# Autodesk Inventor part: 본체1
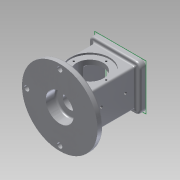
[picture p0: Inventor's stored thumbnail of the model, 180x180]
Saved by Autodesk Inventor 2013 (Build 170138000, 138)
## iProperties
Created: 2019-08
Part Number: 본체1
Material: 알루미늄 6061
Document SubType Name: Modeling
Designer: Administrator
Density: 2.71 g/cm^3
Mass: 1045.81 g
Surface Area: 784.859 cm^2
Volume: 385.908 cm^3
Author: Administrator
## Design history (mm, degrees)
sketch "스케치6"
  geometry: C1 r 67.5 at (0, 0); 1 further point
  constraints: 1 centre point, 1 coincident
  dimensions: "d14" = 135 diameter of C1
extrude "돌출4" new body sketch "스케치6" distance "d15" = 10; taper "d16" = 0 deg
sketch "스케치7"
  geometry: L1 (-37, -33)-(37, -33); L2 (37, -33)-(37, 33); L3 (37, 33)-(-37, 33); L4 (-37, 33)-(-37, -33); L5 (-37, -33)-(37, 33); L6 (37, -33)-(-37, 33); C1 r 67.5 at (0, 0) reference
  constraints: 12 end point, 2 midpoint, 2 parallel, 1 horizontal, 1 perpendicular
  dimensions: "d17" = 74 distance of L3.end L2.end; "d18" = 66 distance of L2.end L1.end
extrude "돌출5" join sketch "스케치7" distance "d19" = 88; taper "d20" = 0 deg
sketch "스케치8"
  geometry: L1 (-46, -41)-(46, -41); L2 (46, -41)-(46, 41); L3 (46, 41)-(-46, 41); L4 (-46, 41)-(-46, -41); L5 (-46, -41)-(46, 41); L6 (46, -41)-(-46, 41); 1 further point
  constraints: 12 end point, 2 midpoint, 2 parallel, 1 horizontal, 1 perpendicular
  dimensions: "d21" = 92 distance of L3.end L2.end; "d22" = 82 distance of L2.end L1.end
extrude "돌출6" join sketch "스케치8" distance "d23" = 10; taper "d24" = 0 deg
sketch "스케치9"
  geometry: L1 (37, -10)-(37, 44); C1 r 35 at (37, 44)
  constraints: 2 end point, 1 centre point, 1 coincident, 1 vertical
  dimensions: "d25" = 54 distance of L1.start L1.end; "d26" = 70 diameter of C1
extrude "돌출7" cut sketch "스케치9" distance "d27" = 3; taper "d28" = 0 deg
sketch "스케치10"
  geometry: C1 r 35 at (0, 0) reference; C2 r 24 at (0, 0); 1 further point
  constraints: 1 centre point, 1 coincident
  dimensions: "d29" = 48 diameter of C2
extrude "돌출8" cut sketch "스케치10" stored distance "d30" = 3; taper "d31" = 0 deg
sketch "스케치11"
  geometry: C1 r 24 at (37, 44) reference; C2 r 35 at (37, 44); 1 further point
  constraints: 1 centre point, 1 coincident
  dimensions: "d32" = 70 diameter of C2
extrude "돌출9" cut sketch "스케치11" distance "d33" = 3; taper "d34" = 0 deg
sketch "스케치12"
  geometry: L1 (-26, -26)-(26, -26); L2 (26, -26)-(26, 26); L3 (26, 26)-(-26, 26); L4 (-26, 26)-(-26, -26); L5 (-26, -26)-(26, 26); L6 (26, -26)-(-26, 26); 1 further point
  constraints: 12 end point, 2 midpoint, 2 parallel, 1 horizontal, 1 perpendicular
  dimensions: "d35" = 52 distance of L3.end L2.end; "d36" = 52 distance of L2.end L1.end
extrude "돌출10" cut sketch "스케치12" distance "d37" = 8; taper "d38" = 0 deg
sketch "스케치13"
  geometry: L1 (-22, -22)-(22, -22); L2 (22, -22)-(22, 22); L3 (22, 22)-(-22, 22); L4 (-22, 22)-(-22, -22); L5 (-22, -22)-(22, 22); L6 (22, -22)-(-22, 22); 1 further point
  constraints: 12 end point, 2 midpoint, 2 parallel, 1 horizontal, 1 perpendicular
  dimensions: "d39" = 44 distance of L3.end L2.end; "d40" = 44 distance of L2.end L1.end
extrude "돌출11" cut sketch "스케치13" distance "d41" = 74; taper "d42" = 0 deg
sketch "스케치14"
  geometry: C1 r 67.5 at (0, 0) reference; C2 r 25 at (0, 0)
  constraints: 1 centre point, 1 coincident
  dimensions: "d43" = 50 diameter of C2
extrude "돌출12" cut sketch "스케치14" distance "d44" = 18; taper "d45" = 0 deg
sketch "스케치16"
  geometry: L1 (0, 0)-(0, 59); L2 (0, 0)-(-59, 0); L3 (0, 0)-(0, -59); C1 r 67.5 at (0, 0) reference; C2 r 4.5 at (0, 59); C3 r 4.5 at (-59, 0); C4 r 4.5 at (0, -59)
  constraints: 6 end point, 3 centre point, 3 coincident, 2 vertical, 1 horizontal
  dimensions: "d49" = 59 distance of L1.start L1.end; "d50" = 9 diameter of C2; "d54" = 59 distance of L1.start L2.end; "d55" = 9 diameter of C3; "d56" = 59 distance of L1.start L3.end; "d57" = 9 diameter of C4
extrude "돌출14" cut sketch "스케치16" distance "d58" = 18; taper "d59" = 0 deg
sketch "스케치17"
  geometry: C1 r 35 at (0, 0) reference; A1 r 29 centre (0, 0) between (0, 29) and (-29, 0); 3 further points
  constraints: 4 point on circle, 1 centre point, 1 coincident
  dimensions: "d61" = 58 diameter of A1
hole "구멍1" sketch "스케치17" at (0, 29), (-29, 0), (0, -29), (29, 0) diameter "d62" = 3.242; stored, may be unused: countersink angle "d66" = 90 deg, drill point angle "d68" = 118 deg; dims "d63" = 4, "d64" = 4, "d65" = 2, "d67" = 6
sketch "스케치18" dims "d69" = 58
  geometry: C1 r 35 at (0, 0) reference; C2 r 1.621 at (-29, 0) reference; C3 r 1.621 at (0, -29) reference; C4 r 1.621 at (29, 0) reference; 6 further points
  constraints: 4 coincident, 1 vertical alignment, 2 other
hole "구멍2" sketch "스케치18" at (0, 29), (-29, 0), (0, -29), (29, 0) diameter "d70" = 3.242; stored, may be unused: countersink angle "d74" = 90 deg, drill point angle "d76" = 118 deg; dims "d71" = 4, "d72" = 4, "d73" = 2, "d75" = 6
sketch "스케치19"
  geometry: L1 (26, 26)-(26, -26) reference; L2 (26, -26)-(-26, -26) reference; L3 (-26, -26)-(-26, 26) reference; L4 (-26, 26)-(26, 26) reference; L5 (-46, -41)-(46, -41) reference; L6 (46, -41)-(46, 41) reference; L7 (46, 41)-(-46, 41) reference; L8 (-46, 41)-(-46, -41) reference; 1 further point
sketch "스케치20"
  geometry: C1 r 25 at (0, 0) reference; C2 r 12.5 at (0, 0)
  constraints: 1 centre point, 1 coincident
  dimensions: "d77" = 25 diameter of C2
extrude "돌출15" cut sketch "스케치20" distance "d78" = 18; taper "d79" = 0 deg
sketch "스케치21"
  geometry: L1 (26, 26)-(26, -26) reference; L2 (26, -26)-(-26, -26) reference; L3 (-26, -26)-(-26, 26) reference; L4 (-26, 26)-(26, 26) reference; L5 (-46, -41)-(46, -41) reference; L6 (46, -41)-(46, 41) reference; L7 (46, 41)-(-46, 41) reference; L8 (-46, 41)-(-46, -41) reference; 1 further point
fillet "모깎기1" dims "d80" = 10
sketch "스케치22"
  geometry: A1 r 10 centre (36, 31) between (46, 31) and (36, 41) reference; A2 r 10 centre (-36, 31) between (-36, 41) and (-46, 31) reference; A3 r 10 centre (-36, -31) between (-46, -31) and (-36, -41) reference; A4 r 10 centre (36, -31) between (36, -41) and (46, -31) reference; 1 further point
hole "구멍3" sketch "스케치22" at (-36, 31), (-36, -31), (36, -31), (36, 31) diameter "d81" = 3.242; stored, may be unused: countersink angle "d85" = 90 deg, drill point angle "d87" = 118 deg; dims "d82" = 4, "d83" = 4, "d84" = 2, "d86" = 6
sketch "스케치23"
  geometry: L1 (33, -10)-(33, 27); L2 (33, 27)-(33, 70)
  constraints: 4 end point, 2 vertical
  dimensions: "d88" = 37 distance of L1.start L1.end; "d89" = 43 distance of L1.end L2.end
hole "구멍4" sketch "스케치23" at (33, 70), (33, 27) diameter "d90" = 4.917; stored, may be unused: countersink angle "d94" = 90 deg, drill point angle "d96" = 118 deg; dims "d91" = 30, "d92" = 4, "d93" = 2, "d95" = 30
sketch "스케치24"
  geometry: C1 r 67.5 at (0, 0) reference; C2 r 59 at (0, 0)
  constraints: 1 centre point, 1 coincident, 1 other
  dimensions: "d97" = 118 diameter of C2
fillet "모깎기2" dims "d98" = 3
fillet "모깎기3" dims "d99" = 3
fillet "모깎기4" dims "d100" = 3
feature "엠보싱1" dims "d104" = 0.5, "d105" = 0
fillet "모깎기5" dims "d106" = 3
fillet "모깎기6" dims "d107" = 3
fillet "모깎기7" dims "d108" = 3
chamfer "모따기2" distance "d109" = 1; stored, may be unused: second distance "d110" = 2, angle "d111" = 45 deg
fillet "모깎기8" dims "d112" = 3
fillet "모깎기9" dims "d113" = 3
fillet "모깎기10" dims "d114" = 3
node "솔리드2"
